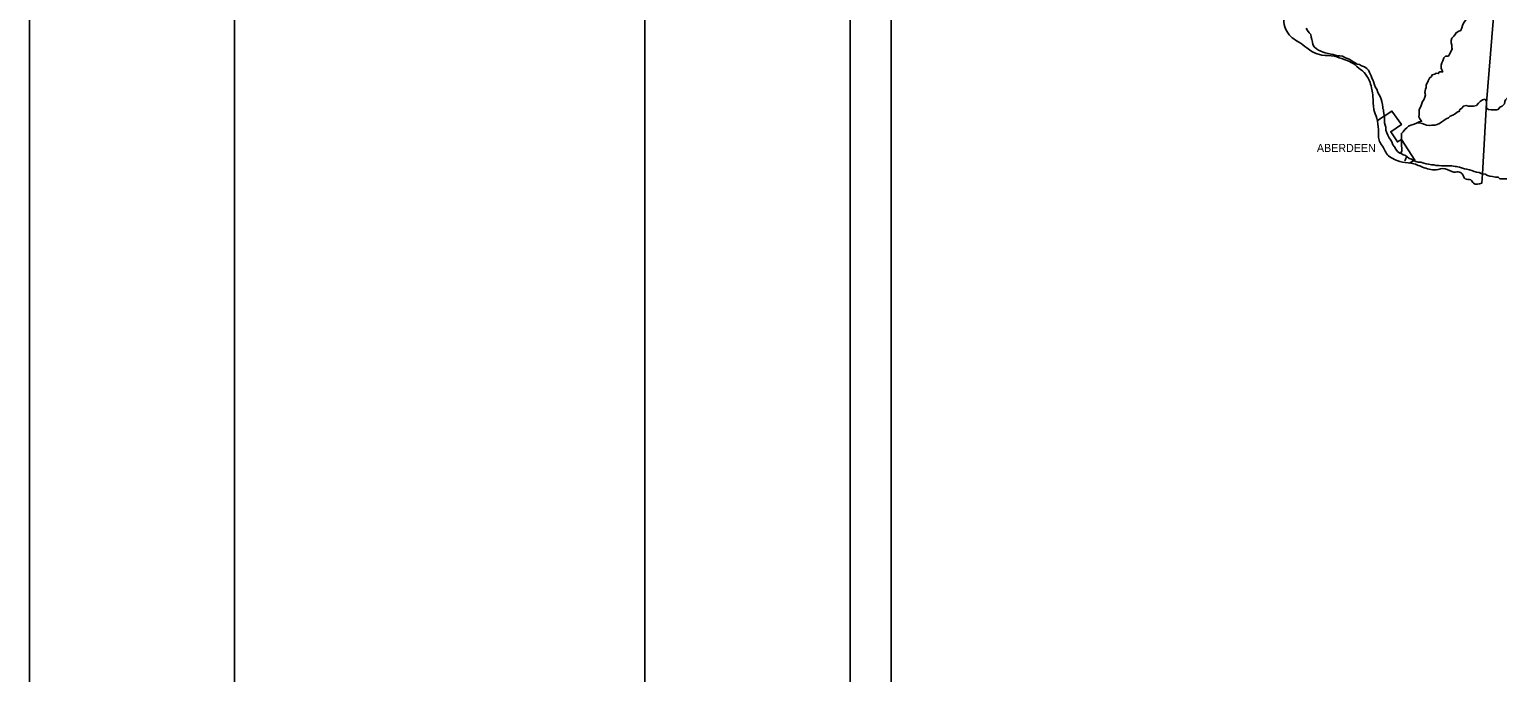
# Model space of a CAD drawing. Extents: x 0 to 34, y 0 to 22.
# Drawn here: x 0 to 3.578, y 14.873 to 16.44 of the extents above; entities that cross this region are included whole.
import ezdxf

# ---------------------------------------------------------------- set-up
doc = ezdxf.new("R2010")
doc.units = 0
for name, color, linetype in [('Default', 7, 'Continuous'), ('SH_Border', 7, 'Continuous'), ('SH_Cut_Line', 7, 'Continuous'), ('SH_Data', 7, 'Continuous')]:
    doc.layers.add(name, color=color, linetype=linetype)

msp = doc.modelspace()

# ---------------------------------------------------------------- linework, layer by layer
at = {"layer": 'Default'}
for points in [[(3.6789, 17.7858), (3.6516, 17.4749), (3.5985, 16.8491), (3.5507, 16.2615), (3.5412, 16.0883), (3.5398, 16.0652)], [(3.4744, 16.4278), (3.4771, 16.4319), (3.4839, 16.436), (3.488, 16.4374), (3.4907, 16.4442), (3.4921, 16.4497), (3.4948, 16.4551), (3.4989, 16.4606), (3.5017, 16.4647), (3.5057, 16.4701), (3.5098, 16.4756), (3.5126, 16.481), (3.5126, 16.4865), (3.5139, 16.4933), (3.5153, 16.5001), (3.518, 16.5056), (3.5207, 16.511), (3.5235, 16.5165), (3.5262, 16.5219), (3.5289, 16.5274), (3.5262, 16.5315), (3.5235, 16.5342)], [(3.1117, 16.4428), (3.1144, 16.4374), (3.1185, 16.4319), (3.1226, 16.4278), (3.124, 16.421), (3.1253, 16.4156), (3.1267, 16.4088), (3.1281, 16.4033), (3.1308, 16.3978), (3.1363, 16.3924), (3.1417, 16.3897), (3.1472, 16.3869), (3.1526, 16.3842), (3.1581, 16.3828), (3.1649, 16.3815), (3.1717, 16.3801), (3.1772, 16.3788), (3.1881, 16.376)], [(3.428, 16.3338), (3.4335, 16.3324), (3.4362, 16.3365), (3.4444, 16.3365), (3.4417, 16.3419), (3.4403, 16.346), (3.4403, 16.3528), (3.4417, 16.3583), (3.4444, 16.3638), (3.4471, 16.3706), (3.4512, 16.3747), (3.458, 16.3747), (3.4608, 16.3801), (3.4648, 16.3869), (3.4676, 16.3924), (3.4662, 16.3951), (3.4662, 16.4019), (3.4648, 16.4074), (3.4648, 16.4128), (3.4662, 16.4183), (3.4717, 16.4237), (3.4744, 16.4278), (3.4744, 16.4278)], [(3.1881, 16.376), (3.1935, 16.376), (3.2003, 16.3747), (3.2072, 16.3706), (3.2126, 16.3692), (3.2181, 16.3665), (3.2235, 16.3624), (3.229, 16.3597), (3.2358, 16.3556), (3.2412, 16.3542), (3.2467, 16.3515), (3.2535, 16.3488), (3.259, 16.3447), (3.2631, 16.3406), (3.2658, 16.3351), (3.2699, 16.3269), (3.2712, 16.3215), (3.274, 16.3174), (3.2767, 16.3106), (3.2781, 16.3051), (3.2808, 16.2983), (3.2835, 16.2942), (3.2862, 16.286), (3.289, 16.2806), (3.2917, 16.2765), (3.2944, 16.2697), (3.2958, 16.2642), (3.2971, 16.2574), (3.2985, 16.2506), (3.2985, 16.2465), (3.2999, 16.2451)], [(3.3817, 16.2124), (3.3871, 16.2151), (3.3926, 16.2165), (3.3885, 16.222), (3.3858, 16.2274), (3.3871, 16.2329), (3.3871, 16.2397), (3.3871, 16.2451), (3.3912, 16.252), (3.3926, 16.2574), (3.3953, 16.2642), (3.398, 16.2683), (3.4008, 16.2751), (3.4021, 16.2806), (3.4008, 16.286), (3.4021, 16.2942), (3.4035, 16.2983), (3.4035, 16.3051), (3.4062, 16.3092), (3.4089, 16.3147), (3.4117, 16.3215), (3.4171, 16.3256), (3.4185, 16.3297), (3.4253, 16.331), (3.428, 16.3338)], [(3.5507, 16.2615), (3.5507, 16.2533), (3.5507, 16.2479), (3.5562, 16.2451), (3.563, 16.2438), (3.5698, 16.2438), (3.5753, 16.2438), (3.5794, 16.2451), (3.5835, 16.2506), (3.5889, 16.2533), (3.5944, 16.2588), (3.5957, 16.2642), (3.5971, 16.2683), (3.6012, 16.2724), (3.6066, 16.2765), (3.6121, 16.2806), (3.6162, 16.2847), (3.623, 16.286), (3.6285, 16.2901), (3.6339, 16.2929), (3.6394, 16.2901), (3.6462, 16.2888), (3.6489, 16.2901), (3.6489, 16.2901)], [(3.2999, 16.2451), (3.2999, 16.2397), (3.3012, 16.2315), (3.3026, 16.2274), (3.3026, 16.2206), (3.3026, 16.2124), (3.304, 16.207), (3.3053, 16.2015), (3.3053, 16.1947), (3.308, 16.1879), (3.3108, 16.1824), (3.3135, 16.1756), (3.3176, 16.1702), (3.3203, 16.1661), (3.323, 16.1592), (3.3271, 16.1538), (3.3299, 16.1483), (3.334, 16.1429), (3.3394, 16.1388), (3.3394, 16.1388), (3.3421, 16.1388)], [(3.4853, 16.2438), (3.4907, 16.2479), (3.4948, 16.2533), (3.5017, 16.2547), (3.5071, 16.2533), (3.5139, 16.2533), (3.5194, 16.2533), (3.5262, 16.2547), (3.5316, 16.2601), (3.5357, 16.2642), (3.5412, 16.2683), (3.5466, 16.2697), (3.5507, 16.2656), (3.5507, 16.2615), (3.5507, 16.2615)], [(3.3626, 16.1143), (3.3762, 16.1211), (3.3435, 16.1715), (3.334, 16.1661), (3.3176, 16.1906), (3.3435, 16.2083), (3.3203, 16.241), (3.2849, 16.2179)], [(3.3421, 16.1388), (3.3449, 16.1442), (3.3449, 16.1511), (3.3435, 16.1565), (3.3435, 16.162), (3.3435, 16.1674), (3.3435, 16.1742), (3.3435, 16.1797), (3.3435, 16.1865), (3.3476, 16.1906), (3.3517, 16.1961), (3.3571, 16.2001), (3.3612, 16.2042), (3.3667, 16.207), (3.3721, 16.2083), (3.3789, 16.2111), (3.3817, 16.2124)], [(3.3817, 16.2124), (3.3871, 16.2124), (3.3939, 16.2111), (3.4008, 16.2083), (3.4049, 16.207), (3.4117, 16.2056), (3.4185, 16.207), (3.4253, 16.207), (3.4308, 16.2083), (3.4362, 16.2111), (3.4417, 16.2151), (3.4471, 16.2179), (3.4526, 16.222), (3.458, 16.2247), (3.4621, 16.2288), (3.4689, 16.2315), (3.4744, 16.2342), (3.4798, 16.2383), (3.4853, 16.241), (3.4853, 16.2438)], [(3.3571, 16.1306), (3.3517, 16.1333), (3.3476, 16.1347), (3.3421, 16.1388)], [(3.3421, 16.1388), (3.3476, 16.1347), (3.3517, 16.1333), (3.3571, 16.1306)], [(3.3517, 16.1197), (3.3544, 16.1252), (3.3571, 16.1306)], [(3.3571, 16.1306), (3.3626, 16.1252), (3.368, 16.1238), (3.3721, 16.1211), (3.3789, 16.1183), (3.3844, 16.117), (3.3912, 16.117), (3.398, 16.1143), (3.4035, 16.1129), (3.4103, 16.1115), (3.4171, 16.1102), (3.4226, 16.1102), (3.428, 16.1088), (3.4348, 16.1088), (3.4417, 16.1074), (3.4485, 16.1074), (3.4539, 16.1074), (3.4608, 16.1074), (3.4662, 16.1074), (3.4744, 16.1061), (3.4771, 16.1061), (3.4853, 16.1047), (3.4921, 16.102), (3.4976, 16.1006), (3.503, 16.0993), (3.5098, 16.0979), (3.5153, 16.0965), (3.5207, 16.0938), (3.5262, 16.0924), (3.533, 16.0911), (3.5398, 16.0883), (3.5412, 16.0883), (3.5412, 16.0883)], [(3.5412, 16.0883), (3.548, 16.087), (3.5535, 16.0843), (3.5589, 16.0829), (3.5657, 16.0815), (3.5726, 16.0802), (3.5794, 16.0802), (3.5835, 16.0761), (3.5903, 16.0761), (3.5971, 16.0761), (3.6025, 16.0761), (3.608, 16.0733), (3.6162, 16.0733), (3.6216, 16.0706), (3.6271, 16.0679), (3.6325, 16.0679), (3.6394, 16.0652), (3.6462, 16.0638), (3.6503, 16.0624), (3.6571, 16.0611), (3.6639, 16.0597), (3.6653, 16.0597), (3.6653, 16.0597)]]:
    msp.add_lwpolyline(points, dxfattribs=at)
msp.add_spline([(3.5398, 16.0652), (3.5194, 16.0652), (3.5126, 16.0733), (3.4989, 16.0761), (3.4935, 16.0856), (3.4853, 16.0924), (3.4717, 16.0924), (3.4498, 16.1006), (3.428, 16.0979), (3.3953, 16.1047), (3.3667, 16.1143), (3.3394, 16.1183), (3.323, 16.1252), (3.3094, 16.1347), (3.3026, 16.147), (3.289, 16.1702), (3.2876, 16.1961), (3.2835, 16.2233), (3.2767, 16.2451), (3.274, 16.2765), (3.2671, 16.3106), (3.2562, 16.331), (3.2399, 16.346), (3.2208, 16.3597), (3.2044, 16.3665), (3.1799, 16.3747), (3.1499, 16.3774), (3.1267, 16.3856), (3.1131, 16.3951), (3.094, 16.4088), (3.0776, 16.4197), (3.064, 16.436), (3.0572, 16.4578), (3.0572, 16.4783), (3.0504, 16.4987), (3.0435, 16.5328), (3.0354, 16.556), (3.0299, 16.5737), (3.0108, 16.5914), (2.989, 16.6051), (2.959, 16.6228), (2.9345, 16.6324), (2.9099, 16.6446), (2.8908, 16.6514), (2.8677, 16.6542), (2.8349, 16.6583), (2.8063, 16.6651), (2.779, 16.6678), (2.7572, 16.6733), (2.7409, 16.6869), (2.7231, 16.7073), (2.7068, 16.7237), (2.6741, 16.7387), (2.64, 16.7442), (2.6032, 16.7496), (2.5609, 16.7428), (2.5391, 16.7305), (2.5118, 16.7223), (2.4709, 16.7142), (2.4464, 16.7073), (2.4191, 16.6937), (2.3864, 16.6869), (2.3577, 16.6814), (2.3373, 16.6746), (2.3168, 16.6787)], degree=3, dxfattribs=at)
at = {"layer": 'SH_Border'}
for points in [[(0.5, 21.5), (1.5, 21.5), (1.5, 0.5), (0.5, 0.5)], [(1.5, 21.5), (33.5, 21.5), (33.5, 0.5), (1.5, 0.5)]]:
    msp.add_lwpolyline(points, close=True, dxfattribs=at)
at = {"layer": 'SH_Cut_Line'}
msp.add_lwpolyline([(0, 0), (34, 0), (34, 22), (0, 22)], close=True, dxfattribs=at)
at = {"layer": 'SH_Data'}
for p, q in [((2, 21), (2, 14)), ((2.1, 20.9), (2.1, 14.1))]:
    msp.add_line(p, q, dxfattribs=at)

# ---------------------------------------------------------------- texts
at = {"layer": 'Default'}
msp.add_text('ABERDEEN', height=0.0195, dxfattribs=at).set_placement((3.1376, 16.1415))

doc.saveas('drawing.dxf')
